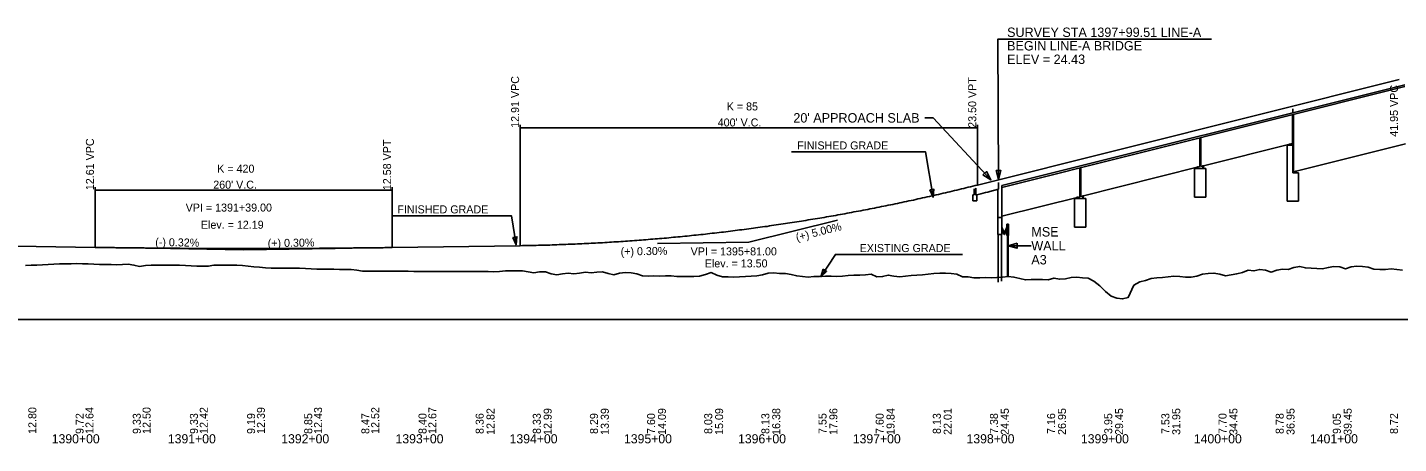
# Model space of a CAD drawing. Extents: x 2360994 to 2383826, y 330623 to 403123.
# Drawn here: x 2371375 to 2372575, y 371764 to 372128 of the extents above; entities that cross this region are included whole.
import ezdxf

# ---------------------------------------------------------------- set-up
doc = ezdxf.new("R2010")
doc.units = 0
for name, color, linetype in [('BR_STRUCTURAL STEEL', 7, 'Continuous'), ('RD_DDB_GradeTX', 7, 'Continuous'), ('RD_DDB_Profile_EX', 7, 'Continuous'), ('RD_DDB_Profile_Lbl', 7, 'Continuous'), ('RD_DDB_Profile_PR', 7, 'Continuous'), ('RD_DDB_StaTX', 7, 'Continuous'), ('RD_DDB_StripGrade', 7, 'Continuous'), ('RD_DDB_VCLbl', 7, 'Continuous'), ('RD_GPK_Profile_Cell', 7, 'Continuous'), ('RD_PD_MedBWall', 7, 'Continuous'), ('RD_TX_Profile', 7, 'Continuous'), ('RD_XS_Bridge', 7, 'Continuous')]:
    doc.layers.add(name, color=color, linetype=linetype)

msp = doc.modelspace()

# ---------------------------------------------------------------- linework, layer by layer
at = {"layer": 'BR_STRUCTURAL STEEL'}
for p, q in [((2372224.7, 371947.1), (2372224.7, 371905.6)), ((2372227.6, 371947.1), (2372227.6, 371906.5))]:
    msp.add_line(p, q, dxfattribs=at)
at = {"layer": 'RD_DDB_GradeTX'}
for p, q in [((2372084.2, 371959.8), (2372006.6, 371940.4)), ((2371926.6, 371939.2), (2372006.6, 371940.4)), ((2371484.6, 371935.1), (2371564.6, 371933.8)), ((2371644.6, 371935), (2371564.6, 371933.8))]:
    msp.add_line(p, q, dxfattribs=at)
at = {"layer": 'RD_DDB_Profile_EX'}
for points in [[(2371373.6, 371920.2), (2371378.6, 371920.3), (2371383.6, 371920.4), (2371388.6, 371920.7), (2371393.6, 371921), (2371398.6, 371921.3), (2371403.6, 371921.4), (2371408.6, 371921.4), (2371413.6, 371921.6), (2371418.6, 371921.7), (2371423.6, 371921.5), (2371428.6, 371921.4), (2371433.6, 371921.1), (2371438.6, 371920.8), (2371443.6, 371920.8), (2371448.6, 371920.8), (2371453.6, 371920.7), (2371458.6, 371920.8), (2371463.6, 371921.1), (2371468.6, 371920.5), (2371473.6, 371919.2), (2371478.6, 371920), (2371483.6, 371920.3), (2371488.6, 371920.4), (2371493.6, 371920.4), (2371498.6, 371920.5), (2371503.6, 371920.5), (2371508.6, 371920.3), (2371513.6, 371920.1), (2371518.6, 371919.8), (2371523.6, 371919.6), (2371528.6, 371919.5), (2371533.6, 371919.4), (2371538.6, 371920.4), (2371543.6, 371920.4), (2371548.6, 371920.4), (2371553.6, 371920.4), (2371558.6, 371920.3), (2371563.6, 371920.1), (2371568.6, 371919.5), (2371573.6, 371919), (2371578.6, 371918.5), (2371583.6, 371918), (2371588.6, 371917.8), (2371593.6, 371917.8), (2371598.6, 371917.7), (2371603.6, 371917.7), (2371608.6, 371917.7), (2371613.6, 371917.6), (2371618.6, 371917.4), (2371623.6, 371917.2), (2371628.6, 371917), (2371633.6, 371916.9), (2371638.6, 371916.8), (2371643.6, 371916.8), (2371648.6, 371916.7), (2371653.6, 371916.7), (2371658.6, 371916.5), (2371663.6, 371915.9), (2371668.6, 371915.2), (2371673.6, 371915.2), (2371678.6, 371915.2), (2371683.6, 371915.2), (2371688.6, 371915.1), (2371693.6, 371915.1), (2371698.6, 371915.1), (2371703.6, 371915), (2371708.6, 371915), (2371713.6, 371914.9), (2371718.6, 371914.9), (2371723.6, 371914.9), (2371728.6, 371914.8), (2371733.6, 371914.8), (2371738.6, 371914.8), (2371743.6, 371914.8), (2371748.6, 371914.8), (2371753.6, 371914.7), (2371758.6, 371914.8), (2371763.6, 371914.7), (2371768.6, 371914.7), (2371773.6, 371914.7), (2371778.6, 371914.7), (2371783.6, 371914.6), (2371788.6, 371914.9), (2371793.6, 371915.5), (2371798.6, 371915.3), (2371803.6, 371915.3), (2371808.6, 371915.4), (2371813.6, 371914.4), (2371818.6, 371913.7), (2371823.6, 371914.6), (2371828.6, 371914.5), (2371833.6, 371912.7), (2371838.6, 371912), (2371843.6, 371912.8), (2371848.6, 371913.5), (2371853.6, 371912.8), (2371858.6, 371913.4), (2371863.6, 371914.1), (2371868.6, 371913.8), (2371873.6, 371914.1)], [(2371873.6, 371914.1), (2371878.6, 371914.6), (2371883.6, 371913.2), (2371888.6, 371911.9), (2371893.6, 371913.3), (2371898.6, 371914), (2371903.6, 371913.8), (2371908.6, 371912.9), (2371913.6, 371911), (2371918.6, 371910.8), (2371923.6, 371910.9), (2371928.6, 371910.8), (2371933.6, 371910.9), (2371938.6, 371910.9), (2371943.6, 371910.5), (2371948.6, 371910.4), (2371953.6, 371910.4), (2371958.6, 371910.4), (2371963.6, 371910.7), (2371968.6, 371912.2), (2371973.6, 371913.9), (2371978.6, 371911.7), (2371983.6, 371910.3), (2371988.6, 371910.1), (2371993.6, 371910), (2371998.6, 371910.2), (2372003.6, 371910.5), (2372008.6, 371910.7), (2372013.6, 371910.9), (2372018.6, 371911.9), (2372023.6, 371913.4), (2372028.6, 371913.6), (2372033.6, 371913.1), (2372038.6, 371913), (2372043.6, 371912.2), (2372048.6, 371911), (2372053.6, 371910.5), (2372058.6, 371910), (2372063.6, 371910.5), (2372068.6, 371910.5), (2372073.6, 371910.7), (2372078.6, 371910.6), (2372083.6, 371910.4), (2372088.6, 371910.7), (2372093.6, 371911.3), (2372098.6, 371911.6), (2372103.6, 371911.7), (2372108.6, 371912), (2372113.6, 371912.5), (2372118.6, 371910.1), (2372123.6, 371910.4), (2372128.6, 371911.7), (2372133.6, 371910.8), (2372138.6, 371910.3), (2372143.6, 371910.7), (2372148.6, 371911.4), (2372153.6, 371911.5), (2372158.6, 371911.9), (2372163.6, 371912.6), (2372168.6, 371913), (2372173.6, 371913.5), (2372178.6, 371913.5), (2372183.6, 371913.1), (2372188.6, 371912.5), (2372193.6, 371910.2), (2372198.6, 371910.1), (2372203.6, 371909.4), (2372208.6, 371909.3), (2372213.6, 371909.6), (2372218.6, 371909.3), (2372223.6, 371909.7), (2372228.6, 371910), (2372233.6, 371910.4), (2372238.6, 371910), (2372243.6, 371908.7), (2372248.6, 371907.4), (2372253.6, 371907.9), (2372258.6, 371907.9), (2372263.6, 371907.8), (2372268.6, 371907.5), (2372273.6, 371909.1), (2372278.6, 371908.1), (2372283.6, 371908.3), (2372288.6, 371909.5), (2372293.6, 371909.8), (2372298.6, 371909.4), (2372303.6, 371908.9), (2372308.6, 371906.5), (2372313.6, 371902.2), (2372318.6, 371897.4), (2372323.6, 371893.4), (2372328.6, 371891.4), (2372333.6, 371890.9), (2372338.6, 371892.2), (2372343.6, 371902.8), (2372348.6, 371905.7), (2372353.6, 371907.1), (2372358.6, 371908.8), (2372363.6, 371909.3), (2372368.6, 371909.7), (2372373.6, 371910.3)], [(2372373.6, 371910.3), (2372378.6, 371910.8), (2372383.6, 371910.4), (2372388.6, 371909.8), (2372393.6, 371910), (2372398.6, 371910.7), (2372403.6, 371912.5), (2372408.6, 371913.2), (2372413.6, 371913.5), (2372418.6, 371912.6), (2372423.6, 371911.1), (2372428.6, 371911.8), (2372433.6, 371912.9), (2372438.6, 371913.9), (2372443.6, 371915.9), (2372448.6, 371915.4), (2372453.6, 371916.6), (2372458.6, 371916.1), (2372463.6, 371914.1), (2372468.6, 371916), (2372473.6, 371916.8), (2372478.6, 371916.7), (2372483.6, 371918.3), (2372488.6, 371919.3), (2372493.6, 371918), (2372498.6, 371917.8), (2372503.6, 371917.3), (2372508.6, 371917.2), (2372513.6, 371918.2), (2372518.6, 371919.3), (2372523.6, 371918.8), (2372528.6, 371917.1), (2372533.6, 371918.8), (2372538.6, 371919.4), (2372543.6, 371919.2), (2372548.6, 371918.5), (2372553.6, 371916.9), (2372558.6, 371916.7), (2372563.6, 371916.6), (2372568.6, 371917.1), (2372573.6, 371916.7), (2372578.6, 371916)]]:
    msp.add_lwpolyline(points, dxfattribs=at)
at = {"layer": 'RD_DDB_Profile_PR'}
for p, q in [((2372206.6, 371990.4), (2372575.6, 372082.6)), ((2371055.6, 371942), (2371434.6, 371935.9)), ((2371694.6, 371935.8), (2371806.6, 371937.4))]:
    msp.add_line(p, q, dxfattribs=at)
for points in [[(2371806.6, 371937.4), (2371814.6, 371937.6), (2371822.6, 371937.7), (2371830.6, 371937.9), (2371838.6, 371938.2), (2371846.6, 371938.5), (2371854.6, 371938.8), (2371862.6, 371939.2), (2371870.6, 371939.6), (2371878.6, 371940), (2371886.6, 371940.5), (2371894.6, 371941), (2371902.6, 371941.6), (2371910.6, 371942.1), (2371918.6, 371942.8), (2371926.6, 371943.4), (2371934.6, 371944.1), (2371942.6, 371944.9), (2371950.6, 371945.6), (2371958.6, 371946.5), (2371966.6, 371947.3), (2371974.6, 371948.2), (2371982.6, 371949.1), (2371990.6, 371950.1), (2371998.6, 371951.1), (2372006.6, 371952.1), (2372014.6, 371953.2), (2372022.6, 371954.3), (2372030.6, 371955.5), (2372038.6, 371956.7), (2372046.6, 371957.9), (2372054.6, 371959.2), (2372062.6, 371960.5), (2372070.6, 371961.8), (2372078.6, 371963.2), (2372086.6, 371964.6), (2372094.6, 371966.1), (2372102.6, 371967.6), (2372110.6, 371969.1), (2372118.6, 371970.7), (2372126.6, 371972.3), (2372134.6, 371973.9), (2372142.6, 371975.6), (2372150.6, 371977.3), (2372158.6, 371979.1), (2372166.6, 371980.9), (2372174.6, 371982.7), (2372182.6, 371984.6), (2372190.6, 371986.5), (2372198.6, 371988.4), (2372206.6, 371990.4)], [(2371434.6, 371935.9), (2371439.8, 371935.8), (2371445, 371935.8), (2371450.2, 371935.7), (2371455.4, 371935.6), (2371460.6, 371935.6), (2371465.8, 371935.5), (2371471, 371935.4), (2371476.2, 371935.4), (2371481.4, 371935.3), (2371486.6, 371935.3), (2371491.8, 371935.2), (2371497, 371935.2), (2371502.2, 371935.1), (2371507.4, 371935.1), (2371512.6, 371935), (2371517.8, 371935), (2371523, 371935), (2371528.2, 371934.9), (2371533.4, 371934.9), (2371538.6, 371934.9), (2371543.8, 371934.9), (2371549, 371934.9), (2371554.2, 371934.9), (2371559.4, 371934.8), (2371564.6, 371934.8), (2371569.8, 371934.8), (2371575, 371934.8), (2371580.2, 371934.8), (2371585.4, 371934.9), (2371590.6, 371934.9), (2371595.8, 371934.9), (2371601, 371934.9), (2371606.2, 371934.9), (2371611.4, 371934.9), (2371616.6, 371935), (2371621.8, 371935), (2371627, 371935), (2371632.2, 371935.1), (2371637.4, 371935.1), (2371642.6, 371935.2), (2371647.8, 371935.2), (2371653, 371935.2), (2371658.2, 371935.3), (2371663.4, 371935.4), (2371668.6, 371935.4), (2371673.8, 371935.5), (2371679, 371935.5), (2371684.2, 371935.6), (2371689.4, 371935.7), (2371694.6, 371935.8)]]:
    msp.add_spline(points, degree=3, dxfattribs=at)
at = {"layer": 'RD_DDB_VCLbl'}
for p, q in [((2371806.6, 372042.9), (2371806.6, 371937.4)), ((2371806.6, 372040.4), (2372206.6, 372040.4)), ((2372206.6, 372042.9), (2372206.6, 371990.4)), ((2371434.6, 371988.4), (2371434.6, 371935.9)), ((2371434.6, 371985.9), (2371694.6, 371985.9)), ((2371694.6, 371988.4), (2371694.6, 371935.8))]:
    msp.add_line(p, q, dxfattribs=at)
at = {"layer": 'RD_GPK_Profile_Cell'}
msp.add_line((2368825.6, 371872.9), (2373925.6, 371872.9), dxfattribs=at)
at = {"layer": 'RD_PD_MedBWall'}
for p, q in [((2372227.9, 371953.7), (2372229.9, 371948.7)), ((2372227.9, 371952.1), (2372229.9, 371947.1)), ((2372229.9, 371948.7), (2372230.4, 371948.7)), ((2372232.4, 371953.7), (2372230.4, 371948.7)), ((2372232.4, 371952.1), (2372230.4, 371947.1)), ((2372232.4, 371946.2), (2372232.4, 371956.2)), ((2372232.4, 371956.2), (2372233.9, 371956.2)), ((2372232.9, 371948.7), (2372233.4, 371948.7)), ((2372232.9, 371910.4), (2372232.9, 371948.7)), ((2372233.4, 371910.4), (2372233.4, 371948.7)), ((2372233.9, 371946.2), (2372233.9, 371956.2)), ((2372229.9, 371947.1), (2372230.4, 371947.1)), ((2372232.4, 371946.2), (2372232.9, 371946.2)), ((2372233.4, 371946.2), (2372233.9, 371946.2))]:
    msp.add_line(p, q, dxfattribs=at)
at = {"layer": 'RD_TX_Profile'}
for p, q in [((2372411.4, 372118), (2372232.6, 372118)), ((2372138.5, 372019.5), (2372044, 372019.5)), ((2371788.7, 371963.6), (2371694.1, 371963.6)), ((2372193.7, 371929.8), (2372098.6, 371929.8))]:
    msp.add_line(p, q, dxfattribs=at)
for points in [[(2372232.6, 372118), (2372224.5, 372118), (2372225.1, 371995)], [(2372160.7, 372049.1), (2372168, 372049.1), (2372218.5, 371994.8)], [(2372138.5, 372019.5), (2372161.1, 372019.5), (2372167.9, 371979.7)], [(2371788.7, 371963.6), (2371798.9, 371963.6), (2371803, 371938.2)], [(2372253.8, 371937.3), (2372247.1, 371937.3), (2372233.4, 371937.3)], [(2372098.6, 371929.8), (2372082.4, 371929.8), (2372069.5, 371910.2)]]:
    msp.add_lwpolyline(points, dxfattribs=at)
for points in [[(2372211.5, 371999.2), (2372218.5, 371994.8), (2372214.7, 372002.1)], [(2372222.9, 372003), (2372225.1, 371995), (2372227.2, 372003)], [(2372165, 371986.1), (2372167.9, 371979.7), (2372168.6, 371986.7)], [(2371800.1, 371944.6), (2371803, 371938.2), (2371803.7, 371945.2)], [(2372241.4, 371939.5), (2372233.4, 371937.3), (2372241.4, 371935.2)], [(2372071.7, 371916.8), (2372069.5, 371910.2), (2372074.7, 371914.8)]]:
    msp.add_lwpolyline(points, close=True, dxfattribs=at)
at = {"layer": 'RD_XS_Bridge'}
for p, q in [((2372227.9, 371989.9), (2372580.6, 372078)), ((2372227.9, 371988.2), (2372580.6, 372076.4)), ((2372482.7, 372056.9), (2372482.7, 372053.6)), ((2372482.2, 372026.7), (2372482.2, 372051.8)), ((2372483.2, 372002), (2372483.2, 372052)), ((2372401.1, 372006.5), (2372401.1, 372031.5)), ((2372402.1, 372006.7), (2372402.1, 372031.8)), ((2372402.1, 372006.7), (2372482.2, 372026.7)), ((2372477.7, 371976.2), (2372477.7, 372025.1)), ((2372477.7, 372025.1), (2372482.7, 372025.1)), ((2372482.7, 372025.1), (2372482.7, 372001.2)), ((2372483.2, 372002), (2372581.1, 372026.5)), ((2372296.1, 371980.2), (2372296.1, 372005.3)), ((2372297.1, 371980.5), (2372401.1, 372006.5)), ((2372297.1, 371980.5), (2372297.1, 372005.5)), ((2372396.6, 372004.9), (2372406.6, 372004.9)), ((2372396.6, 371979.9), (2372396.6, 372004.9)), ((2372406.6, 371979.9), (2372406.6, 372004.9)), ((2372482.7, 372001.2), (2372487.7, 372001.2)), ((2372487.7, 371976.2), (2372487.7, 372001.2)), ((2372203.7, 371987.2), (2372203.7, 371981.7)), ((2372205.1, 371987.6), (2372205, 371987.5)), ((2372205, 371987.5), (2372205, 371981.7)), ((2372205, 371987.5), (2372205, 371981.7)), ((2372205.1, 371987.6), (2372205.1, 371981.7)), ((2372205.1, 371981.7), (2372205.1, 371987.6)), ((2372217.6, 371984.8), (2372225.1, 371986.7)), ((2372224.4, 371986.5), (2372224.4, 371947.1)), ((2372225.1, 371992.5), (2372225.1, 371986.7)), ((2372227.9, 371989.9), (2372227.9, 371947.1)), ((2372202.5, 371981.7), (2372202.5, 371976.7)), ((2372203.7, 371981.7), (2372202.5, 371981.7)), ((2372206.2, 371976.7), (2372202.5, 371976.7)), ((2372205, 371981.7), (2372205.1, 371981.7)), ((2372206.2, 371982), (2372206.2, 371976.7)), ((2372227.9, 371963.2), (2372296.1, 371980.2)), ((2372291.6, 371978.6), (2372301.6, 371978.6)), ((2372291.6, 371953.6), (2372291.6, 371978.6)), ((2372301.6, 371953.6), (2372301.6, 371978.6)), ((2372396.6, 371979.9), (2372406.6, 371979.9)), ((2372477.7, 371976.2), (2372487.7, 371976.2)), ((2372227.9, 371962.1), (2372224.4, 371962.1)), ((2372291.6, 371953.6), (2372301.6, 371953.6)), ((2372227.9, 371947.1), (2372224.4, 371947.1))]:
    msp.add_line(p, q, dxfattribs=at)
for points in [[(2372479.9, 372025.1), (2372479.9, 372026.3), (2372480.4, 372026.3), (2372480.4, 372025.1)], [(2372398.8, 372004.9), (2372398.8, 372006.2), (2372399.3, 372006.2), (2372399.3, 372004.9)], [(2372403.8, 372004.9), (2372403.8, 372007.2), (2372404.3, 372007.2), (2372404.3, 372004.9)], [(2372484.9, 372001.2), (2372484.9, 372002.4), (2372485.4, 372002.4), (2372485.4, 372001.2)], [(2372293.8, 371978.6), (2372293.8, 371979.9), (2372294.3, 371979.9), (2372294.3, 371978.6)], [(2372298.8, 371978.6), (2372298.8, 371980.9), (2372299.3, 371980.9), (2372299.3, 371978.6)]]:
    msp.add_lwpolyline(points, close=True, dxfattribs=at)
msp.add_spline([(2372205, 371981.7), (2372209.6, 371982.8), (2372217.6, 371984.8)], degree=3, dxfattribs=at)

# ---------------------------------------------------------------- texts
at = {"layer": 'RD_DDB_GradeTX'}
for s, rotation, p in [('(+) 5.00%', 14.0362, (2372048.7, 371941.2)), ('(-) 0.32%', 359.077, (2371487.2, 371937.1)), ('(+) 0.30%', 0.8484, (2371585.7, 371936.1)), ('(+) 0.30%', 0.8484, (2371894.5, 371928.8))]:
    msp.add_text(s, height=7, rotation=rotation, dxfattribs=at).set_placement(p)
at = {"layer": 'RD_DDB_Profile_Lbl'}
for s, p in [('VPI = 1391+39.00', (2371513.9, 371967.2)), ('Elev. = 12.19', (2371527.2, 371952.2)), ('VPI = 1395+81.00', (2371955.7, 371928.9)), ('Elev. = 13.50', (2371968.1, 371918.4))]:
    msp.add_text(s, height=7, dxfattribs=at).set_placement(p)
at = {"layer": 'RD_DDB_StaTX'}
for s, p in [('1390+00', (2371396.7, 371764.6)), ('1391+00', (2371498.3, 371764.6)), ('1392+00', (2371597.5, 371764.6)), ('1393+00', (2371697.5, 371764.6)), ('1394+00', (2371797.3, 371764.6)), ('1395+00', (2371897.4, 371764.6)), ('1396+00', (2371997.2, 371764.6)), ('1397+00', (2372097.6, 371764.6)), ('1398+00', (2372197.1, 371764.6)), ('1399+00', (2372297.2, 371764.6)), ('1400+00', (2372396, 371764.6)), ('1401+00', (2372497.6, 371764.6))]:
    msp.add_text(s, height=8, dxfattribs=at).set_placement(p)
at = {"layer": 'RD_DDB_StripGrade'}
for s, p in [('12.91 VPC', (2371805.6, 372040.4)), ('23.50 VPT', (2372205.6, 372040.4)), ('41.95 VPC', (2372574.6, 372032.6)), ('12.61 VPC', (2371433.6, 371985.9)), ('12.58 VPT', (2371693.6, 371985.9)), ('12.80', (2371383.2, 371772.9)), ('12.64', (2371433.2, 371772.9)), ('12.50', (2371483.2, 371772.9)), ('12.42', (2371533.2, 371772.9)), ('12.39', (2371583.2, 371772.9)), ('12.43', (2371633.2, 371772.9)), ('12.52', (2371683.2, 371772.9)), ('12.67', (2371733.2, 371772.9)), ('12.82', (2371784.1, 371772)), ('12.99', (2371834.1, 371772)), ('13.39', (2371884.1, 371772)), ('14.09', (2371934.1, 371772)), ('15.09', (2371984.1, 371772)), ('16.38', (2372034.1, 371772)), ('17.96', (2372084.1, 371772)), ('19.84', (2372134.1, 371772)), ('22.01', (2372184.1, 371772)), ('24.45', (2372234.1, 371772)), ('26.95', (2372284.1, 371772)), ('29.45', (2372334.1, 371772)), ('31.95', (2372384.1, 371772)), ('34.45', (2372434.1, 371772)), ('36.95', (2372484.1, 371772)), ('39.45', (2372534.1, 371772)), ('9.72', (2371424.6, 371772.8)), ('9.33', (2371474.6, 371772.8)), ('9.33', (2371524.6, 371772.8)), ('9.19', (2371574.6, 371772.8)), ('8.85', (2371624.6, 371772.8)), ('8.47', (2371674.6, 371772.8)), ('8.40', (2371724.6, 371772.8)), ('8.36', (2371774.6, 371772.8)), ('8.33', (2371824.6, 371772.8)), ('8.29', (2371874.6, 371772.8)), ('7.60', (2371924.6, 371772.8)), ('8.03', (2371974.6, 371772.8)), ('8.13', (2372024.6, 371772.8)), ('7.55', (2372074.6, 371772.8)), ('7.60', (2372124.6, 371772.8)), ('8.13', (2372174.6, 371772.8)), ('7.38', (2372224.6, 371772.8)), ('7.16', (2372274.6, 371772.8)), ('3.95', (2372324.6, 371772.8)), ('7.53', (2372374.6, 371772.8)), ('7.70', (2372424.6, 371772.8)), ('8.78', (2372474.6, 371772.8)), ('9.05', (2372524.6, 371772.8)), ('8.72', (2372574.6, 371772.8))]:
    msp.add_text(s, height=7, rotation=90, dxfattribs=at).set_placement(p)
at = {"layer": 'RD_DDB_VCLbl'}
for s, p in [('K = 85', (2371987.3, 372055.6)), ("400' V.C.", (2371979.4, 372041.6)), ('K = 420', (2371541.5, 372001.2)), ("260' V.C.", (2371538, 371987.2))]:
    msp.add_text(s, height=7, dxfattribs=at).set_placement(p)
at = {"layer": 'RD_TX_Profile'}
for s, height, p in [('SURVEY STA 1397+99.51 LINE-A', 8.235, (2372232.6, 372119.8)), ('BEGIN LINE-A BRIDGE', 8.235, (2372232.6, 372108)), ('ELEV = 24.43', 8.235, (2372232.6, 372096.2)), ("20' APPROACH SLAB", 8.235, (2372045.6, 372045)), ('FINISHED GRADE', 7, (2372049, 372021.5)), ('FINISHED GRADE', 7, (2371699.1, 371965.6)), ('MSE', 8.24, (2372253.8, 371945.4)), ('EXISTING GRADE', 7, (2372103.6, 371931.8)), ('WALL', 8.24, (2372253.8, 371933.2)), ('A3', 8.24, (2372253.8, 371921))]:
    msp.add_text(s, height=height, dxfattribs=at).set_placement(p)

doc.saveas('drawing.dxf')
